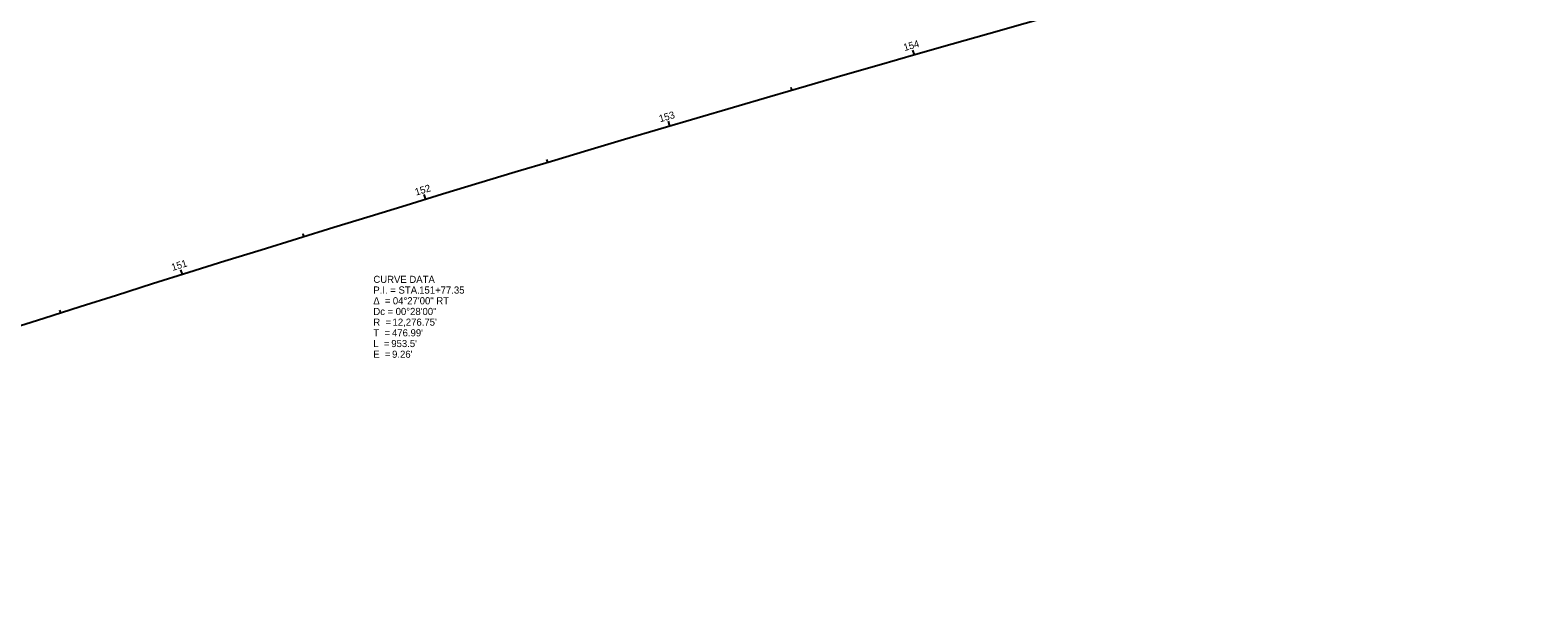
# Model space of a CAD drawing. Extents: x 2124937 to 2129951, y 712967 to 714504.
# Drawn here: x 2126789 to 2127381, y 713498 to 713720 of the extents above; entities that cross this region are included whole.
import ezdxf

# ---------------------------------------------------------------- set-up
doc = ezdxf.new("R2010")
doc.units = 0
for name, color, linetype in [('_CIVIL_CONSTRUCTION', 7, 'Continuous'), ('RW_P_Esmt_TMP', 7, 'Continuous'), ('RW_X_Fee_WL', 7, 'Continuous'), ('SC_Scratch1', 7, 'Continuous')]:
    doc.layers.add(name, color=color, linetype=linetype)

msp = doc.modelspace()

# ---------------------------------------------------------------- linework, layer by layer
at = {"layer": '_CIVIL_CONSTRUCTION'}
msp.add_arc((2130522.17, 701909.21), 12276.75, 104.823574, 109.273574, dxfattribs=at)
at = {"layer": 'RW_P_Esmt_TMP'}
for p, q in [((2127136.52, 713709.89), (2127135.97, 713711.82)), ((2127088.48, 713696.01), (2127088.15, 713697.16)), ((2127040.51, 713681.92), (2127039.94, 713683.84)), ((2126992.59, 713667.65), (2126992.25, 713668.8)), ((2126944.73, 713653.17), (2126944.15, 713655.09)), ((2126896.93, 713638.51), (2126896.58, 713639.65)), ((2126849.19, 713623.65), (2126848.59, 713625.55)), ((2126801.51, 713608.59), (2126801.15, 713609.73))]:
    msp.add_line(p, q, dxfattribs=at)
at = {"layer": 'SC_Scratch1'}
msp.add_arc((2130522.17, 701909.21), 12276.75, 104.823574, 109.273574, dxfattribs=at)

# ---------------------------------------------------------------- texts
at = {"layer": 'RW_P_Esmt_TMP'}
for s, rotation, p in [('154', 16.00834, (2127132.68, 713711.39)), ('153', 16.47505, (2127036.73, 713683.42)), ('152', 16.94175, (2126940.93, 713654.63)), ('151', 17.40845, (2126845.37, 713625.07))]:
    msp.add_text(s, height=2.8, rotation=rotation, dxfattribs=at).set_placement(p)
at = {"layer": 'RW_X_Fee_WL'}
for s, p in [('CURVE DATA', (2126924.15, 713620.38)), ('P.I. = STA. ', (2126924.15, 713616.18)), ('151+77.35', (2126942.14, 713616.18)), ('Δ  = ', (2126924.15, 713611.98)), ('Dc = ', (2126924.15, 713607.78)), ('04°27\'00" RT', (2126931.8, 713611.98)), ('00°28\'00"', (2126932.9, 713607.78)), ('R  = ', (2126924.15, 713603.58)), ("12,276.75'", (2126931.69, 713603.58)), ('T  = ', (2126924.15, 713599.38)), ('L  = ', (2126924.15, 713595.18)), ("953.5'", (2126931.19, 713595.18)), ("476.99'", (2126931.47, 713599.38)), ('E  = ', (2126924.15, 713590.98)), ("9.26'", (2126931.5, 713590.98))]:
    msp.add_text(s, height=2.8, dxfattribs=at).set_placement(p)

doc.saveas('drawing.dxf')
